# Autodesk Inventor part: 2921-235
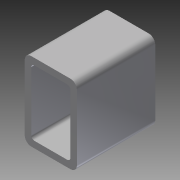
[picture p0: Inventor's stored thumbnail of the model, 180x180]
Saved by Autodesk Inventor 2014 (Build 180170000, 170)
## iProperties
Company: NHTSA/VRTC
Created: 2012-08
Part Number: 2921-235
Material: Steel, Mild
Document SubType Name: Modeling
Designer: Mike Vanvoorhis
Density: 7.86 g/cm^3
Mass: 770.392 g
Surface Area: 368.855 cm^2
Volume: 98.0143 cm^3
Project: CHILD SIDE IMPACT SLED
Description: HONEYCOMB FRAME BUMPER TUBE
Stock Number: T.S. 3" x 2" x 1/4" x 0'-3" (76.2)
Appearance: Steel
Author: Dave Walker
Title: Honeycomb Frame Bumper Tube
Subject: Child Side Impact Sled
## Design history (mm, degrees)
sketch "Sketch1"
  geometry: L1 (6.35, 0)-(44.45, 0); L2 (50.8, 6.35)-(50.8, 69.85); L3 (44.45, 76.2)-(6.35, 76.2); L4 (0, 69.85)-(0, 6.35); L5 (9.525, 69.85)-(41.275, 69.85); L6 (44.45, 66.675)-(44.45, 9.525); L7 (41.275, 6.35)-(9.525, 6.35); L8 (6.35, 9.525)-(6.35, 66.675); A1 r 6.35 centre (6.35, 69.85) between (6.35, 76.2) and (0, 69.85); A2 r 6.35 centre (44.45, 69.85) between (50.8, 69.85) and (44.45, 76.2); A3 r 6.35 centre (44.45, 6.35) between (44.45, 0) and (50.8, 6.35); A4 r 6.35 centre (6.35, 6.35) between (0, 6.35) and (6.35, 0); A5 r 3.175 centre (41.275, 66.675) between (44.45, 66.675) and (41.275, 69.85); A6 r 3.175 centre (41.275, 9.525) between (41.275, 6.35) and (44.45, 9.525); A7 r 3.175 centre (9.525, 9.525) between (6.35, 9.525) and (9.525, 6.35); A8 r 3.175 centre (9.525, 66.675) between (9.525, 69.85) and (6.35, 66.675); 12 further points
  constraints: 16 end point, 16 point on circle, 16 point on line, 16 tangent, 8 centre point, 6 equal radius, 4 parallel, 2 perpendicular, 1 horizontal, 23 other
  dimensions: "d0" = 50.8 distance of point (0, 76.2) point (50.8, 76.2); "d1" = 76.2 distance of point (50.8, 76.2) point (50.8, 0); "d2" = 6.35 radius of A1; "d5" = 6.35 distance between parallel lines of L8 L4; "d6" = 3.175 radius of A5
extrude "Extrusion1" new body sketch "Sketch1" distance "d3" = 76.2; taper "d4" = 0 deg
body "Solid1"
